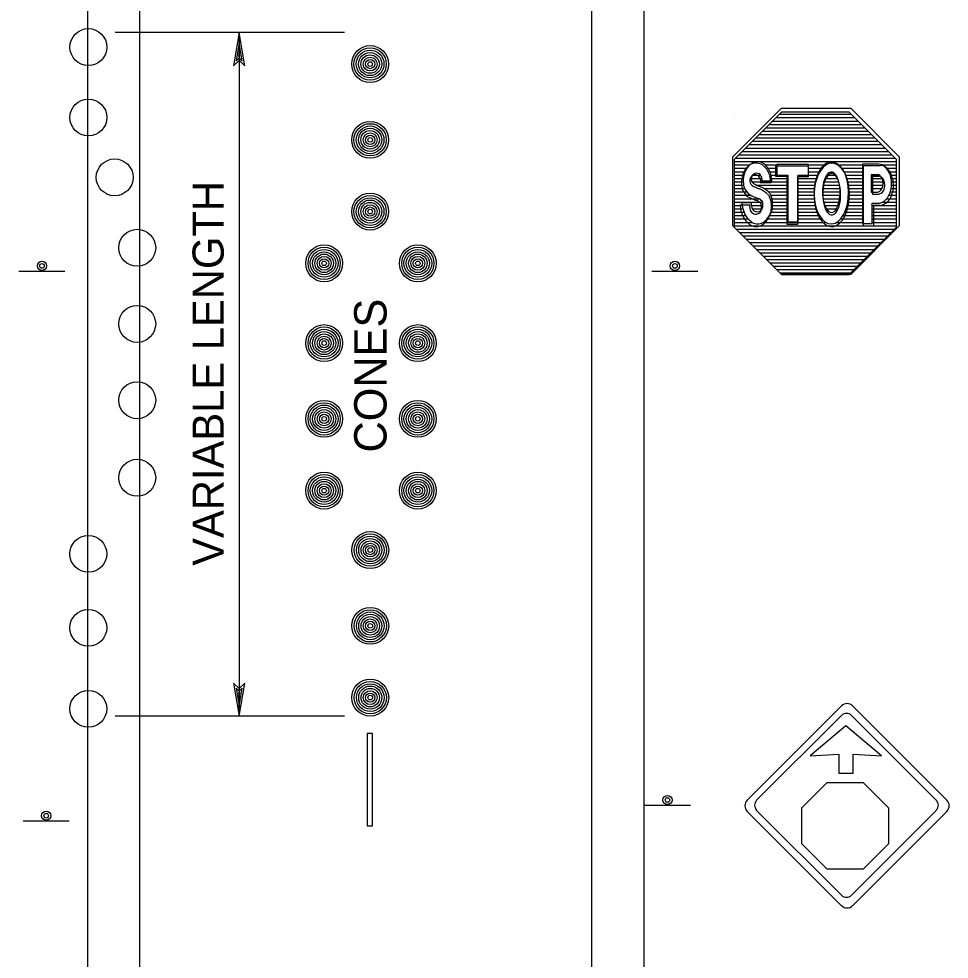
# Model space of a CAD drawing. Extents: x 1314 to 1530, y 165 to 444.
# Drawn here: x 1362.84 to 1411.64, y 296.15 to 345.46 of the extents above; entities that cross this region are included whole.
import ezdxf

# ---------------------------------------------------------------- set-up
doc = ezdxf.new("R2010")
doc.units = 0
for name, color, linetype in [('Level 1', 7, 'Continuous'), ('Level 10', 7, 'Continuous'), ('Level 2', 7, 'Continuous'), ('Level 44', 7, 'Continuous'), ('Level 60', 7, 'Continuous')]:
    doc.layers.add(name, color=color, linetype=linetype)

msp = doc.modelspace()

# ---------------------------------------------------------------- linework, layer by layer
at = {"layer": 'Level 1'}
for points in [[(1374.4, 344.732), (1374.11, 342.99), (1374.4, 343.281), (1374.69, 342.99), (1374.4, 344.732), (1374.4, 344.198), (1374.243, 343.252), (1374.4, 343.408), (1374.557, 343.252), (1374.4, 344.198), (1374.4, 343.658), (1374.371, 343.495), (1374.4, 343.524), (1374.429, 343.495), (1374.4, 343.658), (1374.4, 343.524)], [(1374.4, 308.884), (1374.69, 310.626), (1374.4, 310.335), (1374.11, 310.626), (1374.4, 308.884), (1374.4, 309.418), (1374.557, 310.364), (1374.4, 310.208), (1374.243, 310.364), (1374.4, 309.418), (1374.4, 309.958), (1374.429, 310.121), (1374.4, 310.091), (1374.371, 310.121), (1374.4, 309.958), (1374.4, 310.091)]]:
    msp.add_lwpolyline(points, dxfattribs=at)
at = {"layer": 'Level 10'}
for p, q in [((1366.452, 414.007), (1366.452, 189.638)), ((1369.178, 414.007), (1369.178, 189.638)), ((1392.884, 414.007), (1392.884, 189.638)), ((1395.628, 414.007), (1395.628, 189.638)), ((1379.919, 344.732), (1367.892, 344.732)), ((1374.4, 344.732), (1374.4, 308.884)), ((1369.178, 331.59), (1369.186, 331.582)), ((1379.919, 308.884), (1367.892, 308.884))]:
    msp.add_line(p, q, dxfattribs=at)
msp.add_lwpolyline([(1405.24, 305.411), (1407.127, 305.411), (1408.46, 304.079), (1408.46, 302.198), (1407.127, 300.865), (1405.24, 300.865), (1403.914, 302.198), (1403.914, 304.079)], close=True, dxfattribs=at)
for centre, radius in [((1366.489, 343.975), 0.968), ((1381.268, 343.085), 0.968), ((1381.268, 343.085), 0.847), ((1381.268, 343.085), 0.726), ((1381.268, 343.085), 0.605), ((1381.268, 343.085), 0.484), ((1381.268, 343.085), 0.363), ((1381.268, 343.085), 0.242), ((1381.268, 343.085), 0.121), ((1366.489, 340.283), 0.968), ((1381.268, 339.112), 0.968), ((1381.268, 339.112), 0.847), ((1381.268, 339.112), 0.726), ((1381.268, 339.112), 0.605), ((1381.268, 339.112), 0.484), ((1381.268, 339.112), 0.363), ((1381.268, 339.112), 0.242), ((1381.268, 339.112), 0.121), ((1367.87, 337.144), 0.968), ((1381.268, 335.348), 0.968), ((1381.268, 335.348), 0.847), ((1381.268, 335.348), 0.726), ((1381.268, 335.348), 0.605), ((1381.268, 335.348), 0.484), ((1381.268, 335.348), 0.363), ((1381.268, 335.348), 0.242), ((1381.268, 335.348), 0.121), ((1369.053, 333.451), 0.968), ((1378.857, 332.636), 0.968), ((1378.857, 332.636), 0.847), ((1378.857, 332.636), 0.726), ((1383.77, 332.636), 0.968), ((1383.77, 332.636), 0.847), ((1383.77, 332.636), 0.726), ((1378.857, 332.636), 0.605), ((1378.857, 332.636), 0.484), ((1378.857, 332.636), 0.363), ((1378.857, 332.636), 0.242), ((1383.77, 332.636), 0.605), ((1383.77, 332.636), 0.484), ((1383.77, 332.636), 0.363), ((1383.77, 332.636), 0.242), ((1378.857, 332.636), 0.121), ((1383.77, 332.636), 0.121), ((1369.054, 329.458), 0.968), ((1378.857, 328.453), 0.968), ((1383.77, 328.453), 0.968), ((1378.857, 328.453), 0.847), ((1378.857, 328.453), 0.726), ((1378.857, 328.453), 0.605), ((1378.857, 328.453), 0.484), ((1383.77, 328.453), 0.847), ((1383.77, 328.453), 0.726), ((1383.77, 328.453), 0.605), ((1383.77, 328.453), 0.484), ((1378.857, 328.453), 0.363), ((1378.857, 328.453), 0.242), ((1378.857, 328.453), 0.121), ((1383.77, 328.453), 0.363), ((1383.77, 328.453), 0.242), ((1383.77, 328.453), 0.121), ((1369.054, 325.456), 0.968), ((1378.857, 324.48), 0.968), ((1383.77, 324.48), 0.968), ((1378.857, 324.48), 0.847), ((1378.857, 324.48), 0.726), ((1378.857, 324.48), 0.605), ((1378.857, 324.48), 0.484), ((1383.77, 324.48), 0.847), ((1383.77, 324.48), 0.726), ((1383.77, 324.48), 0.605), ((1383.77, 324.48), 0.484), ((1378.857, 324.48), 0.363), ((1378.857, 324.48), 0.242), ((1378.857, 324.48), 0.121), ((1383.77, 324.48), 0.363), ((1383.77, 324.48), 0.242), ((1383.77, 324.48), 0.121), ((1369.054, 321.393), 0.968), ((1378.857, 320.716), 0.968), ((1378.857, 320.716), 0.847), ((1383.77, 320.716), 0.968), ((1383.77, 320.716), 0.847), ((1378.857, 320.716), 0.726), ((1378.857, 320.716), 0.605), ((1378.857, 320.716), 0.484), ((1378.857, 320.716), 0.363), ((1383.77, 320.716), 0.726), ((1383.77, 320.716), 0.605), ((1383.77, 320.716), 0.484), ((1383.77, 320.716), 0.363), ((1378.857, 320.716), 0.242), ((1378.857, 320.716), 0.121), ((1383.77, 320.716), 0.242), ((1383.77, 320.716), 0.121), ((1381.273, 317.6), 0.968), ((1366.488, 317.401), 0.968), ((1381.273, 317.6), 0.847), ((1381.273, 317.6), 0.726), ((1381.273, 317.6), 0.605), ((1381.273, 317.6), 0.484), ((1381.273, 317.6), 0.363), ((1381.273, 317.6), 0.242), ((1381.273, 317.6), 0.121), ((1366.488, 313.524), 0.968), ((1381.273, 313.627), 0.968), ((1381.273, 313.627), 0.847), ((1381.273, 313.627), 0.726), ((1381.273, 313.627), 0.605), ((1381.273, 313.627), 0.484), ((1381.273, 313.627), 0.363), ((1381.273, 313.627), 0.242), ((1381.273, 313.627), 0.121), ((1381.273, 309.863), 0.968), ((1381.273, 309.863), 0.847), ((1366.488, 309.277), 0.968), ((1381.273, 309.863), 0.726), ((1381.273, 309.863), 0.605), ((1381.273, 309.863), 0.484), ((1381.273, 309.863), 0.363), ((1381.273, 309.863), 0.242), ((1381.273, 309.863), 0.121)]:
    msp.add_circle(centre, radius, dxfattribs=at)
at = {"layer": 'Level 2'}
for p, q in [((1381.108, 307.975), (1381.108, 303.137)), ((1381.398, 307.975), (1381.108, 307.975)), ((1381.398, 303.137), (1381.398, 307.975)), ((1381.108, 303.137), (1381.398, 303.137))]:
    msp.add_line(p, q, dxfattribs=at)
at = {"layer": 'Level 44'}
for p, q in [((1402.842, 340.566), (1400.356, 338.079)), ((1400.356, 340.566), (1400.356, 340.566)), ((1406.383, 340.566), (1402.842, 340.566)), ((1408.87, 338.079), (1406.383, 340.566)), ((1400.356, 338.079), (1400.356, 334.537)), ((1402.601, 337.81), (1402.601, 337.265)), ((1404.258, 337.81), (1402.601, 337.81)), ((1404.258, 337.25), (1404.258, 337.81)), ((1405.447, 337.882), (1405.463, 337.883)), ((1407.956, 337.839), (1407.085, 337.839)), ((1407.085, 337.839), (1407.085, 334.722)), ((1408.87, 334.537), (1408.87, 338.079)), ((1402.55, 337.182), (1402.55, 337.741)), ((1402.55, 337.741), (1404.249, 337.741)), ((1404.249, 337.741), (1404.249, 337.168)), ((1405.425, 337.339), (1405.448, 337.343)), ((1407.144, 334.577), (1407.144, 337.77)), ((1407.144, 337.77), (1408.038, 337.77)), ((1407.878, 337.279), (1407.538, 337.279)), ((1407.538, 337.279), (1407.538, 336.372)), ((1407.538, 337.279), (1407.538, 336.372)), ((1407.878, 337.279), (1407.538, 337.279)), ((1402.289, 336.848), (1401.744, 336.848)), ((1402.346, 336.939), (1401.814, 336.939)), ((1403.138, 337.182), (1402.55, 337.182)), ((1402.601, 337.265), (1403.175, 337.265)), ((1403.138, 334.671), (1403.138, 337.182)), ((1403.175, 337.265), (1403.175, 334.814)), ((1404.249, 337.168), (1403.69, 337.168)), ((1403.69, 337.168), (1403.69, 334.671)), ((1403.713, 334.814), (1403.713, 337.25)), ((1403.713, 337.25), (1404.258, 337.25)), ((1407.61, 337.197), (1407.61, 336.268)), ((1407.957, 337.197), (1407.61, 337.197)), ((1407.957, 337.197), (1407.61, 337.197)), ((1407.61, 337.197), (1407.61, 336.268)), ((1407.538, 336.372), (1407.871, 336.372)), ((1407.538, 336.372), (1407.871, 336.372)), ((1400.766, 335.819), (1401.255, 335.819)), ((1407.61, 336.268), (1407.95, 336.268)), ((1407.61, 336.268), (1407.95, 336.268)), ((1400.671, 335.702), (1401.171, 335.702)), ((1407.601, 334.722), (1407.601, 335.785)), ((1407.601, 335.785), (1407.928, 335.785)), ((1407.992, 335.673), (1407.674, 335.665)), ((1407.674, 335.665), (1408.008, 335.665)), ((1407.674, 335.665), (1407.674, 334.577)), ((1400.83, 335.07), (1400.827, 335.072)), ((1403.175, 334.814), (1403.713, 334.814)), ((1400.356, 334.537), (1402.842, 332.051)), ((1403.69, 334.671), (1403.138, 334.671)), ((1406.383, 332.051), (1408.87, 334.537)), ((1407.085, 334.722), (1407.601, 334.722)), ((1407.674, 334.577), (1407.144, 334.577)), ((1362.842, 332.23), (1365.261, 332.23)), ((1396.037, 332.23), (1398.456, 332.23)), ((1402.842, 332.051), (1406.383, 332.051)), ((1405.989, 309.427), (1401.041, 304.486)), ((1411.515, 304.486), (1406.574, 309.427)), ((1401.536, 304.482), (1405.989, 308.929)), ((1406.514, 308.929), (1410.962, 304.482)), ((1406.225, 308.391), (1404.354, 306.814)), ((1408.094, 306.814), (1406.225, 308.391)), ((1404.354, 306.814), (1405.849, 306.895)), ((1405.849, 306.895), (1405.849, 305.896)), ((1406.599, 305.896), (1406.599, 306.895)), ((1406.599, 306.895), (1408.094, 306.814)), ((1405.849, 305.896), (1406.594, 305.896)), ((1395.648, 304.224), (1398.067, 304.224)), ((1400.746, 304.196), (1400.746, 304.196)), ((1401.041, 303.899), (1405.989, 298.952)), ((1401.044, 303.899), (1401.041, 303.899)), ((1405.989, 299.503), (1401.536, 303.953)), ((1410.962, 303.953), (1406.514, 299.503)), ((1406.574, 298.952), (1411.515, 303.899)), ((1363.064, 303.401), (1365.483, 303.401))]:
    msp.add_line(p, q, dxfattribs=at)
msp.add_lwpolyline([(1409.019, 334.599), (1406.471, 332.051), (1402.842, 332.051), (1400.294, 334.599), (1400.294, 338.228), (1402.842, 340.776), (1406.471, 340.776), (1409.019, 338.228)], close=True, dxfattribs=at)
for points in [[(1402.551, 340.275), (1406.667, 340.275)], [(1402.729, 340.452), (1406.496, 340.452)], [(1402.197, 339.921), (1407.028, 339.921)], [(1402.374, 340.098), (1406.851, 340.098)], [(1401.666, 339.389), (1407.559, 339.389)], [(1401.843, 339.567), (1407.382, 339.567)], [(1402.02, 339.744), (1407.197, 339.744)], [(1401.134, 338.858), (1408.091, 338.858)], [(1401.312, 339.035), (1407.913, 339.035)], [(1401.489, 339.212), (1407.736, 339.212)], [(1400.603, 338.327), (1408.621, 338.327)], [(1400.781, 338.504), (1408.445, 338.504)], [(1400.957, 338.681), (1408.267, 338.681)], [(1400.356, 337.973), (1408.87, 337.973)], [(1400.356, 337.796), (1401.177, 337.796)], [(1400.426, 338.15), (1408.799, 338.15)], [(1401.992, 337.796), (1402.601, 337.796)], [(1404.258, 337.796), (1405.079, 337.796)], [(1405.831, 337.796), (1407.085, 337.796)], [(1408.118, 337.796), (1408.87, 337.796)], [(1400.356, 337.618), (1401.028, 337.618)], [(1400.356, 337.442), (1400.929, 337.442)], [(1402.147, 337.618), (1402.601, 337.618)], [(1402.246, 337.442), (1402.601, 337.442)], [(1404.258, 337.618), (1404.917, 337.618)], [(1404.258, 337.442), (1404.796, 337.442)], [(1406.001, 337.618), (1407.085, 337.618)], [(1406.114, 337.442), (1407.085, 337.442)], [(1408.345, 337.618), (1408.87, 337.618)], [(1408.458, 337.442), (1408.87, 337.442)], [(1400.356, 337.265), (1400.879, 337.265)], [(1400.356, 337.088), (1400.845, 337.088)], [(1400.356, 336.91), (1400.837, 336.91)], [(1401.269, 337.088), (1401.821, 337.088)], [(1401.297, 336.91), (1403.175, 336.91)], [(1401.347, 337.265), (1401.743, 337.265)], [(1402.296, 337.265), (1402.601, 337.265)], [(1402.339, 337.088), (1403.175, 337.088)], [(1403.713, 337.088), (1404.655, 337.088)], [(1403.713, 336.91), (1404.612, 336.91)], [(1404.258, 337.265), (1404.719, 337.265)], [(1405.066, 336.91), (1405.838, 336.91)], [(1405.115, 337.088), (1405.781, 337.088)], [(1405.2, 337.265), (1405.696, 337.265)], [(1406.192, 337.265), (1407.085, 337.265)], [(1406.255, 337.088), (1407.085, 337.088)], [(1406.298, 336.91), (1407.085, 336.91)], [(1407.538, 337.265), (1407.948, 337.265)], [(1407.538, 337.088), (1408.118, 337.088)], [(1407.538, 336.91), (1408.161, 336.91)], [(1408.543, 337.265), (1408.87, 337.265)], [(1408.586, 337.088), (1408.87, 337.088)], [(1408.607, 336.91), (1408.87, 336.91)], [(1400.356, 336.733), (1400.858, 336.733)], [(1400.356, 336.556), (1400.909, 336.556)], [(1400.356, 336.379), (1401.021, 336.379)], [(1401.524, 336.733), (1403.175, 336.733)], [(1401.921, 336.556), (1403.175, 336.556)], [(1402.162, 336.379), (1403.175, 336.379)], [(1403.713, 336.733), (1404.584, 336.733)], [(1403.713, 336.379), (1404.556, 336.379)], [(1403.72, 336.556), (1404.563, 336.556)], [(1404.995, 336.379), (1405.909, 336.379)], [(1405.009, 336.556), (1405.909, 336.556)], [(1405.016, 336.733), (1405.881, 336.733)], [(1406.333, 336.733), (1407.085, 336.733)], [(1406.348, 336.556), (1407.085, 336.556)], [(1406.362, 336.379), (1407.085, 336.379)], [(1407.531, 336.733), (1408.168, 336.733)], [(1407.538, 336.556), (1408.111, 336.556)], [(1408.543, 336.379), (1408.87, 336.379)], [(1408.593, 336.556), (1408.87, 336.556)], [(1408.614, 336.733), (1408.87, 336.733)], [(1400.356, 336.202), (1401.248, 336.202)], [(1400.356, 336.025), (1401.666, 336.025)], [(1400.356, 335.848), (1401.85, 335.848)], [(1402.296, 336.202), (1403.175, 336.202)], [(1402.346, 336.025), (1403.175, 336.025)], [(1402.374, 335.848), (1403.175, 335.848)], [(1403.713, 336.202), (1404.556, 336.202)], [(1403.713, 336.025), (1404.57, 336.025)], [(1403.713, 335.848), (1404.592, 335.848)], [(1404.995, 336.202), (1405.915, 336.202)], [(1405.016, 336.025), (1405.894, 336.025)], [(1405.051, 335.848), (1405.859, 335.848)], [(1406.313, 335.848), (1407.085, 335.848)], [(1406.341, 336.025), (1407.085, 336.025)], [(1406.355, 336.202), (1407.085, 336.202)], [(1408.118, 335.848), (1408.87, 335.848)], [(1408.36, 336.025), (1408.87, 336.025)], [(1408.479, 336.202), (1408.87, 336.202)], [(1400.356, 335.67), (1400.788, 335.67)], [(1400.356, 335.493), (1400.822, 335.493)], [(1400.356, 335.317), (1400.879, 335.317)], [(1401.269, 335.67), (1401.871, 335.67)], [(1401.326, 335.493), (1401.829, 335.493)], [(1402.303, 335.317), (1403.175, 335.317)], [(1402.36, 335.493), (1403.175, 335.493)], [(1402.374, 335.67), (1403.175, 335.67)], [(1403.713, 335.67), (1404.62, 335.67)], [(1403.713, 335.493), (1404.669, 335.493)], [(1403.713, 335.317), (1404.733, 335.317)], [(1405.108, 335.67), (1405.81, 335.67)], [(1405.186, 335.493), (1405.717, 335.493)], [(1406.157, 335.317), (1407.085, 335.317)], [(1406.227, 335.493), (1407.085, 335.493)], [(1406.277, 335.67), (1407.085, 335.67)], [(1407.601, 335.67), (1408.87, 335.67)], [(1407.601, 335.493), (1408.87, 335.493)], [(1407.601, 335.317), (1408.87, 335.317)], [(1400.356, 335.14), (1400.964, 335.14)], [(1400.356, 334.962), (1401.106, 334.962)], [(1402.091, 334.962), (1403.175, 334.962)], [(1402.218, 335.14), (1403.175, 335.14)], [(1403.713, 335.14), (1404.825, 335.14)], [(1403.713, 334.962), (1404.953, 334.962)], [(1405.938, 334.962), (1407.085, 334.962)], [(1406.064, 335.14), (1407.085, 335.14)], [(1407.601, 335.14), (1408.87, 335.14)], [(1407.601, 334.962), (1408.87, 334.962)], [(1400.356, 334.785), (1401.312, 334.785)], [(1400.356, 334.609), (1408.87, 334.609)], [(1400.461, 334.431), (1408.763, 334.431)], [(1401.857, 334.785), (1405.165, 334.785)], [(1405.725, 334.785), (1407.085, 334.785)], [(1407.601, 334.785), (1408.87, 334.785)], [(1400.639, 334.254), (1408.586, 334.254)], [(1400.816, 334.077), (1408.409, 334.077)], [(1400.993, 333.9), (1408.232, 333.9)], [(1401.17, 333.723), (1408.054, 333.723)], [(1401.347, 333.546), (1407.878, 333.546)], [(1401.524, 333.369), (1407.701, 333.369)], [(1401.701, 333.192), (1407.524, 333.192)], [(1401.878, 333.014), (1407.346, 333.014)], [(1402.056, 332.837), (1407.169, 332.837)], [(1402.232, 332.66), (1406.992, 332.66)], [(1402.41, 332.483), (1406.816, 332.483)], [(1402.594, 332.306), (1406.638, 332.306)], [(1402.764, 332.129), (1406.461, 332.129)]]:
    msp.add_lwpolyline(points, dxfattribs=at)
for centre, radius in [((1364.056, 332.501), 0.242), ((1364.056, 332.501), 0.121), ((1397.251, 332.501), 0.242), ((1397.251, 332.501), 0.121), ((1396.862, 304.495), 0.242), ((1396.862, 304.495), 0.121), ((1364.278, 303.671), 0.242), ((1364.278, 303.671), 0.121)]:
    msp.add_circle(centre, radius, dxfattribs=at)
for centre, radius, start, end in [((1401.728, 337.002), 0.967, 123.3662, 155.6734), ((1401.798, 337.089), 0.944, 123.3662, 155.6734), ((1401.506, 337.306), 0.591, 46.1369, 121.3987), ((1401.581, 337.385), 0.577, 46.1369, 121.3987), ((1401.34, 337.069), 0.974, 14.564, 49.0063), ((1407.909, 337.326), 0.517, 44.8528, 85.0441), ((1407.99, 337.245), 0.53, 44.8528, 85.0441), ((1402.099, 336.885), 1.355, 157.7332, 177.1392), ((1402.16, 336.975), 1.322, 157.7332, 177.1392), ((1401.554, 337.08), 0.287, 113.8064, 172.2407), ((1401.532, 337.057), 0.3, 47.3017, 109.0119), ((1401.391, 337.004), 0.439, 350.4412, 39.3244), ((1401.259, 336.982), 0.998, 14.564, 49.0063), ((1400.995, 336.915), 1.348, 0.6952, 17.1451), ((1407.825, 336.984), 0.307, 35.1198, 79.3117), ((1407.825, 336.984), 0.307, 35.1198, 79.3117), ((1407.747, 337.098), 0.794, 29.2241, 48.5308), ((1407.747, 337.098), 0.794, 29.2241, 48.5308), ((1407.824, 337.012), 0.814, 29.2241, 48.5308), ((1407.824, 337.012), 0.814, 29.2241, 48.5308), ((1407.737, 337.021), 0.843, 13.0674, 33.762), ((1407.813, 336.933), 0.864, 13.0674, 33.762), ((1401.932, 336.848), 1.19, 174.8171, 195.9183), ((1401.997, 336.938), 1.161, 174.8171, 195.9183), ((1401.443, 336.951), 0.268, 164.131, 238.1476), ((1401.478, 336.993), 0.294, 113.8064, 172.2407), ((1401.52, 337.039), 0.262, 164.131, 238.1476), ((1401.455, 336.97), 0.308, 47.3017, 109.0119), ((1402.348, 338.361), 1.821, 237.9816, 250.979), ((1401.311, 336.916), 0.449, 350.4412, 39.3244), ((1400.905, 336.824), 1.381, 0.6952, 17.1452), ((1407.904, 336.895), 0.315, 35.1198, 79.3117), ((1407.904, 336.895), 0.315, 35.1198, 79.3117), ((1407.682, 336.893), 0.477, 8.6031, 34.217), ((1407.682, 336.893), 0.477, 8.6031, 34.217), ((1407.664, 336.831), 0.507, 350.3416, 15.2342), ((1407.664, 336.831), 0.507, 350.3416, 15.2342), ((1407.757, 336.801), 0.489, 8.6031, 34.217), ((1407.757, 336.801), 0.489, 8.6031, 34.217), ((1407.739, 336.738), 0.52, 350.3417, 15.2342), ((1407.739, 336.738), 0.52, 350.3417, 15.2342), ((1406.979, 336.772), 1.639, 3.3903, 15.6597), ((1407.3, 336.804), 1.317, 349.7521, 2.7916), ((1407.3, 336.804), 1.317, 349.7521, 2.7916), ((1407.037, 336.678), 1.68, 3.3903, 15.6597), ((1401.582, 336.813), 0.847, 200.4481, 235.1107), ((1401.656, 336.904), 0.826, 200.4481, 235.1107), ((1402.291, 338.305), 1.866, 237.9816, 250.979), ((1401.195, 335.33), 1.305, 46.2465, 67.9263), ((1401.278, 335.457), 1.274, 46.2465, 67.9263), ((1403.882, 337.787), 2.226, 219.479, 223.426), ((1407.799, 336.717), 0.352, 281.9191, 325.7868), ((1407.799, 336.717), 0.352, 281.9191, 325.7868), ((1407.877, 336.622), 0.361, 281.9191, 325.7868), ((1407.877, 336.622), 0.361, 281.9191, 325.7868), ((1407.712, 336.769), 0.453, 326.5086, 357.0313), ((1407.712, 336.769), 0.453, 326.5086, 357.0313), ((1407.788, 336.675), 0.464, 326.5086, 357.0313), ((1407.788, 336.675), 0.464, 326.5086, 357.0313), ((1406.908, 336.907), 1.721, 338.3153, 348.6699), ((1406.964, 336.816), 1.764, 338.3153, 348.6699), ((1407.365, 336.711), 1.35, 349.7521, 2.7916), ((1407.365, 336.711), 1.35, 349.7521, 2.7916), ((1402.396, 335.892), 1.629, 182.3841, 204.9519), ((1403.751, 341.648), 6.134, 244.4624, 248.8312), ((1403.772, 341.623), 5.987, 244.4624, 248.8312), ((1401.992, 335.812), 0.743, 179.0171, 193.5172), ((1401.436, 335.554), 0.387, 34.2083, 74.1552), ((1401.513, 335.676), 0.377, 34.2083, 74.1552), ((1401.524, 335.715), 0.346, 352.5761, 30.4776), ((1403.864, 337.718), 2.281, 219.479, 223.4261), ((1400.96, 335.622), 1.359, 5.9097, 21.9865), ((1401.048, 335.742), 1.326, 5.9097, 21.9865), ((1400.494, 335.746), 1.878, 351.247, 3.9864), ((1407.943, 335.969), 0.18, 259.7909, 293.5419), ((1407.79, 336.535), 0.765, 286.602, 299.809), ((1407.944, 336.337), 0.518, 295.3838, 322.6188), ((1408.025, 336.232), 0.531, 295.3838, 322.6188), ((1407.726, 336.578), 0.84, 318.2922, 338.6031), ((1407.726, 336.578), 0.84, 318.2922, 338.6031), ((1407.802, 336.478), 0.86, 318.2922, 338.6031), ((1407.802, 336.478), 0.86, 318.2922, 338.6031), ((1402.34, 335.776), 1.669, 182.3841, 204.9519), ((1401.927, 335.694), 0.761, 179.0172, 193.5172), ((1401.569, 335.55), 0.382, 186.8728, 222.7449), ((1401.643, 335.672), 0.373, 186.8728, 222.7449), ((1401.593, 335.705), 0.363, 230.6966, 271.4573), ((1401.49, 335.556), 0.345, 275.4374, 314.0625), ((1401.566, 335.677), 0.337, 275.4374, 314.0625), ((1401.34, 335.553), 0.459, 326.253, 358.7323), ((1401.447, 335.595), 0.355, 352.5761, 30.4776), ((1401.42, 335.674), 0.447, 326.253, 358.7323), ((1400.843, 335.76), 1.512, 325.5092, 343.2894), ((1400.935, 335.877), 1.476, 325.5092, 343.2894), ((1400.392, 335.626), 1.924, 351.247, 3.9864), ((1408.025, 335.855), 0.184, 259.7909, 293.5419), ((1407.867, 336.435), 0.784, 286.602, 299.8091), ((1401.876, 335.636), 1.189, 208.4154, 233.6553), ((1401.943, 335.755), 1.16, 208.4154, 233.6553), ((1401.581, 335.239), 0.531, 232.0536, 292.7397), ((1401.518, 335.585), 0.372, 230.6966, 271.4573), ((1401.378, 335.401), 0.868, 293.1413, 324.9906), ((1401.457, 335.527), 0.847, 293.1413, 324.9906), ((1401.506, 335.107), 0.544, 232.0536, 292.7397), ((1406.28, 309.135), 0.414, 45, 135), ((1406.251, 308.666), 0.372, 45, 135), ((1401.336, 304.192), 0.414, 135, 225), ((1401.801, 304.217), 0.372, 135, 225), ((1410.7, 304.217), 0.372, 315, 45), ((1411.224, 304.192), 0.414, 315, 45), ((1406.251, 299.768), 0.372, 225, 315), ((1406.28, 299.248), 0.414, 225, 315)]:
    msp.add_arc(centre, radius, start, end, dxfattribs=at)
for centre, major_axis, ratio, start_param, end_param in [((1405.456, 336.326), (-0.011, -1.623), 0.558644, 3.185857, 9.451311), ((1405.476, 336.22), (-0.011, -1.663), 0.558644, 3.185857, 4.129398), ((1405.476, 336.22), (-0.011, -1.663), 0.558644, 0.656861, 3.168126), ((1405.456, 336.363), (0.005, -1.06), 0.432619, 3.239639, 9.473919), ((1405.476, 336.258), (0.006, -1.086), 0.432619, 3.239639, 3.888884), ((1405.476, 336.258), (0.006, -1.086), 0.432619, 0.881967, 3.190734), ((1405.476, 336.22), (-0.011, -1.663), 0.558644, 4.129576, 6.939747), ((1405.476, 336.258), (0.006, -1.086), 0.432619, 3.890436, 7.165085)]:
    msp.add_ellipse(centre, major_axis=major_axis, ratio=ratio, start_param=start_param, end_param=end_param, dxfattribs=at)

# ---------------------------------------------------------------- texts
at = {"layer": 'Level 10'}
msp.add_text('CONES', height=1.6956, rotation=90, dxfattribs=at).set_placement((1382.128, 322.716))
at = {"layer": 'Level 60'}
msp.add_text('VARIABLE LENGTH', height=1.63524, rotation=90, dxfattribs=at).set_placement((1373.589, 316.776))

doc.saveas('drawing.dxf')
